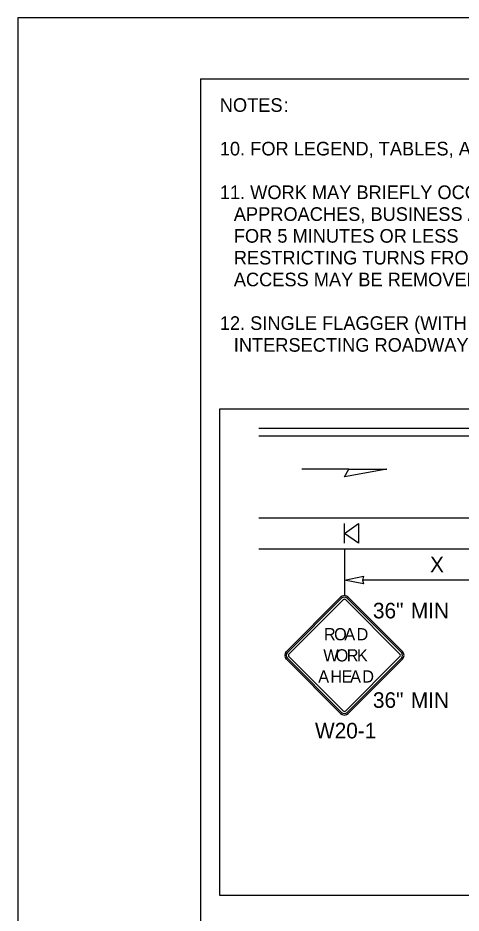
# Model space of a CAD drawing. Extents: x 99999.1 to 100095.7, y 99995 to 100010.7.
# Drawn here: x 100019.062 to 100021.34, y 100006.09 to 100010.687 of the extents above; entities that cross this region are included whole.
import ezdxf

# ---------------------------------------------------------------- set-up
doc = ezdxf.new("R2010")
doc.units = 0
for name, color, linetype in [('RD_ED_ShoulderPavedEdge', 7, 'Continuous'), ('RD_MK_LineDblYellowCenter', 7, 'Continuous'), ('RD_MK_LineEdgeWhite', 7, 'Continuous'), ('SH_GI_GeneralNotesBodyText', 7, 'Continuous'), ('SH_GI_PlotLimits', 7, 'Continuous'), ('SH_GI_SheetBorder', 7, 'Continuous'), ('TR_SN_ConstructionSigns', 7, 'Continuous'), ('TR_WZ_PortableSignMountBlk-Org', 7, 'Continuous'), ('TR_WZ_WorkZoneDetails', 7, 'Continuous'), ('TR_WZ_WorkZoneTextCurrent', 7, 'Continuous')]:
    doc.layers.add(name, color=color, linetype=linetype)

msp = doc.modelspace()

# ---------------------------------------------------------------- linework, layer by layer
at = {"layer": 'RD_ED_ShoulderPavedEdge'}
msp.add_line((100020.3, 100007.9602), (100024.9804, 100007.9602), dxfattribs=at)
at = {"layer": 'RD_MK_LineDblYellowCenter'}
for p, q in [((100020.3, 100008.5802), (100023.7402, 100008.5802)), ((100020.3, 100008.5402), (100023.7402, 100008.5402))]:
    msp.add_line(p, q, dxfattribs=at)
at = {"layer": 'RD_MK_LineEdgeWhite'}
msp.add_line((100020.3, 100008.1202), (100024.9804, 100008.1202), dxfattribs=at)
at = {"layer": 'SH_GI_PlotLimits'}
msp.add_lwpolyline([(100019.0625, 99999.6875), (100036.0625, 99999.6875), (100036.0625, 100010.6875), (100019.0625, 100010.6875)], close=True, dxfattribs=at)
at = {"layer": 'SH_GI_SheetBorder'}
for q in [(100020, 100000), (100035.75, 100010.375)]:
    msp.add_line((100020, 100010.375), q, dxfattribs=at)
at = {"layer": 'TR_SN_ConstructionSigns'}
for p, q in [((100020.7203, 100007.712), (100020.4419, 100007.4336)), ((100020.7258, 100007.7065), (100020.4474, 100007.428)), ((100020.4551, 100007.4203), (100020.7335, 100007.6987)), ((100020.7468, 100007.6987), (100021.0252, 100007.4203)), ((100021.0329, 100007.428), (100020.7545, 100007.7065)), ((100021.0385, 100007.4336), (100020.76, 100007.712)), ((100020.7335, 100007.1286), (100020.4551, 100007.4071)), ((100021.0252, 100007.4071), (100020.7468, 100007.1286)), ((100020.4419, 100007.3938), (100020.7203, 100007.1154)), ((100020.4474, 100007.3993), (100020.7258, 100007.1209)), ((100020.7545, 100007.1209), (100021.0329, 100007.3993)), ((100020.76, 100007.1154), (100021.0385, 100007.3938))]:
    msp.add_line(p, q, dxfattribs=at)
for centre, radius, start, end in [((100020.7402, 100007.6921), 0.0281, 45, 135), ((100020.7402, 100007.6921), 0.0203, 45, 135), ((100020.7402, 100007.6921), 0.00937, 45, 135), ((100020.4617, 100007.4137), 0.0281, 135, 225), ((100020.4617, 100007.4137), 0.0203, 135, 225), ((100020.4617, 100007.4137), 0.00937, 135, 225), ((100021.0186, 100007.4137), 0.00937, 315, 45), ((100021.0186, 100007.4137), 0.0203, 315, 45), ((100021.0186, 100007.4137), 0.0281, 315, 45), ((100020.7402, 100007.1353), 0.00937, 225, 315), ((100020.7402, 100007.1353), 0.0281, 225, 315), ((100020.7402, 100007.1353), 0.0203, 225, 315)]:
    msp.add_arc(centre, radius, start, end, dxfattribs=at)
at = {"layer": 'TR_WZ_PortableSignMountBlk-Org'}
msp.add_line((100020.7402, 100007.9902), (100020.7402, 100008.0902), dxfattribs=at)
msp.add_lwpolyline([(100020.7402, 100008.0401), (100020.812, 100008.0902), (100020.812, 100007.9902)], close=True, dxfattribs=at)
at = {"layer": 'TR_WZ_WorkZoneDetails'}
for p, q in [((100020.7624, 100008.3695), (100020.5213, 100008.3695)), ((100020.7402, 100007.9605), (100020.7402, 100007.7202)), ((100021.5964, 100007.8002), (100020.8339, 100007.8002))]:
    msp.add_line(p, q, dxfattribs=at)
for points in [[(100020.959, 100008.3695), (100020.7402, 100008.3309), (100020.7624, 100008.3695)], [(100020.7402, 100007.8002), (100020.8384, 100007.8195), (100020.8339, 100007.8002), (100020.8384, 100007.781)]]:
    msp.add_lwpolyline(points, close=True, dxfattribs=at)
at = {"layer": 'TR_WZ_WorkZoneTextCurrent'}
msp.add_lwpolyline([(100020.1, 100008.6802), (100025.15, 100008.6802), (100025.15, 100006.1804), (100020.1, 100006.1804)], close=True, dxfattribs=at)

# ---------------------------------------------------------------- texts
at = {"layer": 'SH_GI_GeneralNotesBodyText'}
for s, p in [('NOTES', (100020.1, 100010.205)), (':', (100020.4275, 100010.205)), ('10. FOR LEGEND, TABLES, AND ADDITIONAL NOTES: SEE TC323, SHEET 1.', (100020.1, 100009.981)), ('11. WORK MAY BRIEFLY OCCUR WITHIN LANE CLOSURE ACROSS INTERSECTING ROADWAY ', (100020.1, 100009.757)), ('APPROACHES, BUSINESS ACCESSES, OR DRIVEWAYS. ', (100020.172, 100009.645)), ('FOR 5 MINUTES OR LESS', (100020.172, 100009.533)), ('RESTRICTING TURNS FROM MAINLINE. CHANNELIZATION DEVICES DELINEATING APPROACH OR ', (100020.172, 100009.421)), ('ACCESS MAY BE REMOVED OR RELOCATED AS NEEDED.', (100020.172, 100009.309)), ('12. SINGLE FLAGGER (WITH RED FLAG/ RED GLOW CONE FLASHLIGHT) MAY BE ADDED TO THE ', (100020.1, 100009.085)), ('INTERSECTING ROADWAY APPROACH TO HELP GUIDE ALTERNATING & TURNING TRAFFIC.', (100020.172, 100008.973))]:
    msp.add_text(s, height=0.07, rotation=360, dxfattribs=at).set_placement(p)
at = {"layer": 'TR_SN_ConstructionSigns'}
for s, p in [('36"', (100020.8869, 100007.6035)), ('MIN', (100021.0819, 100007.6035)), ('36"', (100020.8869, 100007.1439)), ('MIN', (100021.0819, 100007.1439)), ('W20-1', (100020.5892, 100006.9871))]:
    msp.add_text(s, height=0.08, rotation=360, dxfattribs=at).set_placement(p)
for s, p in [('R', (100020.6351, 100007.491)), ('O', (100020.6872, 100007.491)), ('A', (100020.74, 100007.491)), ('D', (100020.8027, 100007.491)), ('W', (100020.6318, 100007.3824)), ('O', (100020.6951, 100007.3824)), ('R', (100020.7523, 100007.3824)), ('K', (100020.8047, 100007.3824)), ('A', (100020.6058, 100007.2739)), ('H', (100020.6683, 100007.2739)), ('E', (100020.7258, 100007.2739)), ('A', (100020.7695, 100007.2739)), ('D', (100020.832, 100007.2739))]:
    msp.add_text(s, height=0.0625, dxfattribs=at).set_placement(p)
at = {"layer": 'TR_WZ_WorkZoneTextCurrent'}
msp.add_text('X', height=0.08, rotation=360, dxfattribs=at).set_placement((100021.1804, 100007.8402))

doc.saveas('drawing.dxf')
